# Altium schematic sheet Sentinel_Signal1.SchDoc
size A4; SheetNumber: 1; SheetTotal: 10
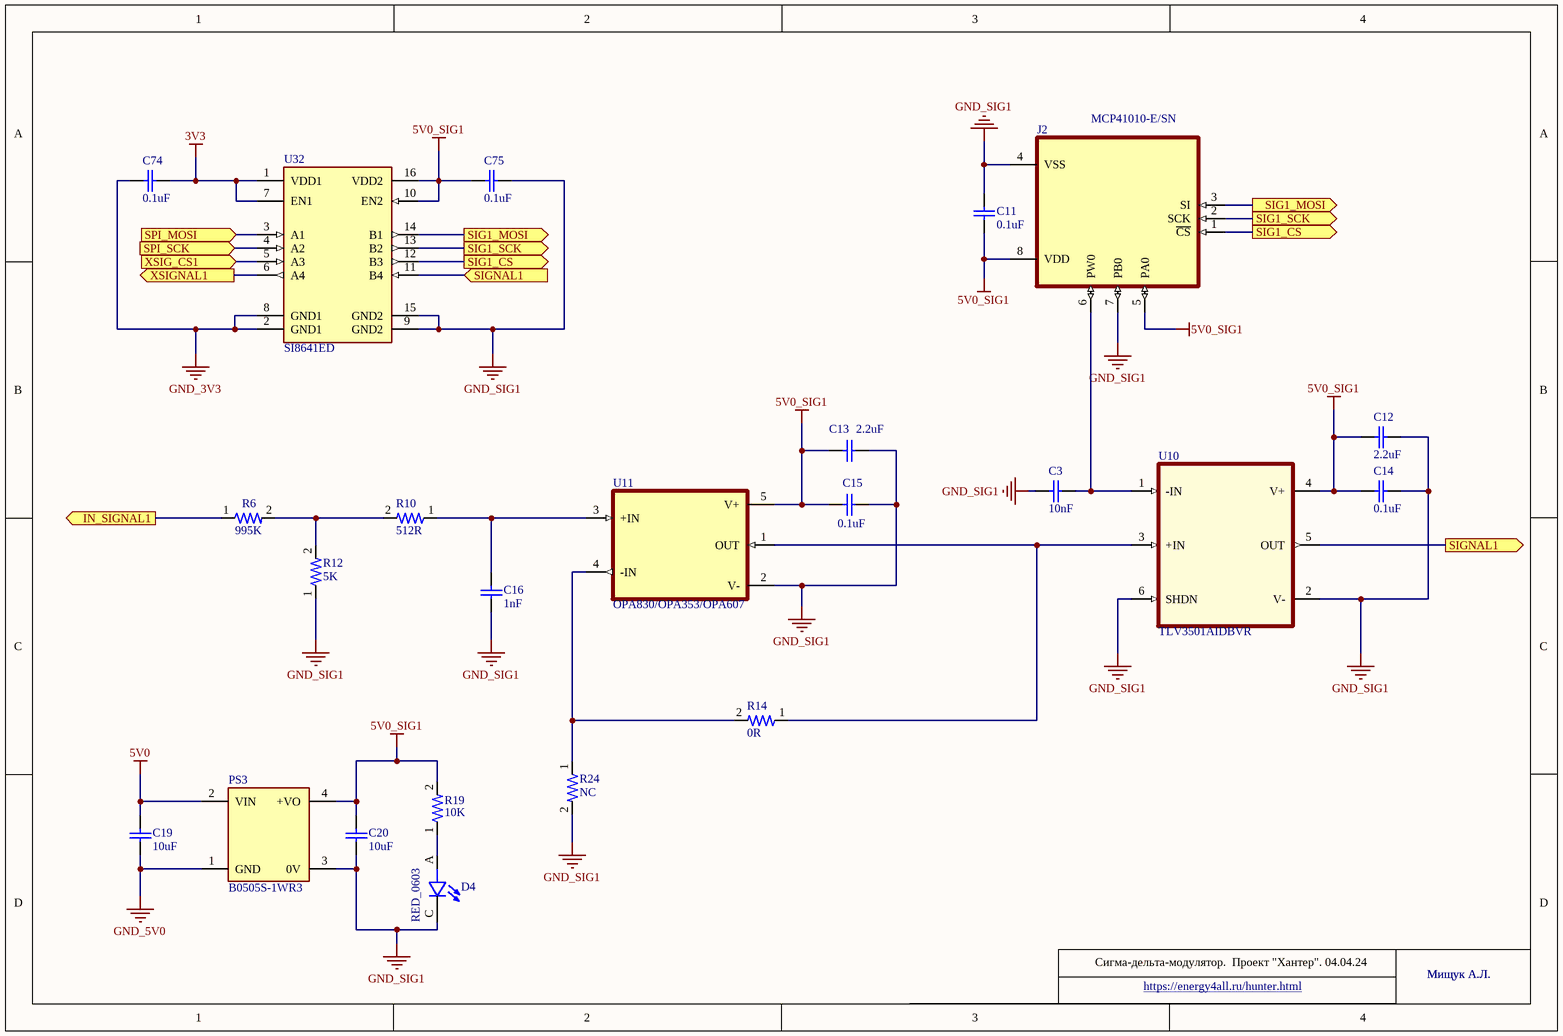
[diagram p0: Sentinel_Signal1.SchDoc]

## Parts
C3  10nF  [CAP_0603]
C11  0.1uF  [CAP_0603]
C12  2.2uF  [CAP_0603]
C13  2.2uF  [CAP_0603]
C14  0.1uF  [CAP_0603]
C15  0.1uF  [CAP_0603]
C16  1nF  [CAP_0603]
C19  10uF  [CAP_0603]
C20  10uF  [CAP_0603]
C74  0.1uF  [CAP_0603]
C75  0.1uF  [CAP_0603]
D4  RED_0603  [led_0603]
J2  MCP41010-E/SN  [MCP41010-E_SN]
PS3  B0505S-1WR3  [B0503S-1W]
R6  995K  [RES_2512]
R10  512R  [RESC1608X50N]
R12  5K  [RES_1206]
R14  0R  [RESC1608X50N]
R19  10K  [RESC1608X50N]
R24  NC  [RESC1608X50N]
U10  TLV3501AIDBVR  [TLV3501AIDBVR]
U11  OPA830/OPA353/OPA607  [OPA735AIDBVR]
U32  SI8641ED  [SI8641ED]

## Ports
IN_SIGNAL1 (out), SIG1_CS (out), SIG1_MOSI (out), SIG1_SCK (out), SIGNAL1 (in), SIGNAL1 (out), SPI_MOSI (in), SPI_SCK (in), XSIG_CS1 (in), XSIGNAL1 (out)

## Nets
3V3: C74.1 U32.1(VDD1) U32.7(EN1)
5V0: C19.2 PS3.2(VIN)
5V0_SIG1: C11.1 C12.2 C13.2 C14.2 C15.2 C20.2 C75.2 J2.5(PA0) J2.8(VDD) PS3.4(+VO) R19.2 U10.4(V+) U11.5(V+) U32.10(EN2) U32.16(VDD2)
GND_3V3: C74.2 U32.2(GND1) U32.8(GND1)
GND_5V0: C19.1 PS3.1(GND)
GND_SIG1: C3.2 C11.2 C12.1 C13.1 C14.1 C15.1 C16.1 C20.1 C75.1 D4.C J2.4(VSS) J2.7(PB0) PS3.3(0V) R12.1 R24.2 U10.2(V-) U10.6(SHDN) U11.2(V-) U32.9(GND2) U32.15(GND2)
IN_SIGNAL1: R6.1 ; port IN_SIGNAL1
SIG1_CS: J2.1(~{CS}) U32.12(B3) ; port SIG1_CS
SIG1_MOSI: J2.3(SI) U32.14(B1) ; port SIG1_MOSI
SIG1_SCK: J2.2(SCK) U32.13(B2) ; port SIG1_SCK
SIGNAL1: U10.5(OUT) U32.11(B4) ; port SIGNAL1
SPI_MOSI: U32.3(A1) ; port SPI_MOSI
SPI_SCK: U32.4(A2) ; port SPI_SCK
XSIG_CS1: U32.5(A3) ; port XSIG_CS1
XSIGNAL1: U32.6(A4) ; port XSIGNAL1
NetC3_1: C3.1 J2.6(PW0) U10.1(-IN)
NetC16_2: C16.2 R10.1 U11.3(+IN)
NetD4_A: D4.A R19.1
NetR6_2: R6.2 R10.2 R12.2
NetR14_1: R14.1 U10.3(+IN) U11.1(OUT)
NetR14_2: R14.2 R24.1 U11.4(-IN)

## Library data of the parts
C3 C11-C16 C19 C20 C74 C75 = CAP_0603
D4 = led_0603: LED Indication - Discrete 3.1V 0603 _1608 Metric_; MP: LTW-C191TLA; MF: Lite-On
PS3 = B0505S-1WR3: Isolated Module DC DC Converter 1 Output 5V 200mA 4.5V - 5.5V Input; MF: Mornsun America, LLC
R6 = RES_2512: 2512 1% 1W; MP: 1-2176071-4
R10 R14 R19 R24 = RES_0603: 1% 0.1W; MP: 1-2176071-4
R12 = RES_1206: 1% 1/4W; MP: 1-2176071-4
U10 = TLV3501AIDBVR: 4.5ns, Rail-to-Rail, High Speed Comparator with Shutdown 6-SOT-23 -40 to 125
U11 = OPA735AIDR
U32 = SI8641ED: General Purpose Digital Isolator 2500Vrms 4 Channel 150Mbps 35kV/Âµs CMTI 16-SOIC _0.154, 3.90mm Width_; MP: SI8641BB-B-IS1; MF: Silicon Labs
